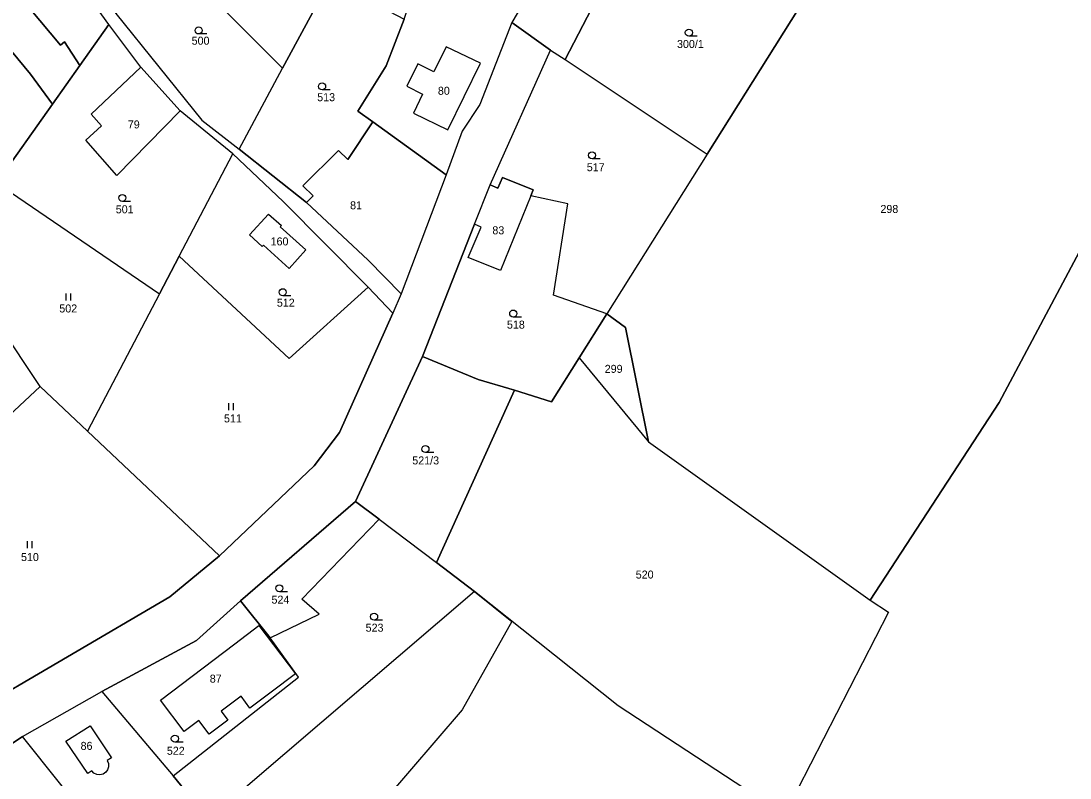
# Model space of a CAD drawing. Extents: x -590606 to -587796, y -1065936 to -1062515.
# Drawn here: x -589413.2 to -589190.3, y -1065080 to -1064919.2 of the extents above; entities that cross this region are included whole.
import ezdxf

# ---------------------------------------------------------------- set-up
doc = ezdxf.new("R2010")
doc.units = 0
for name, color, linetype in [('Parcela nároku', 7, 'Continuous'), ('Vnější obvod_ Studené', 7, 'Continuous'), ('Vrstva 30', 7, 'Continuous')]:
    doc.layers.add(name, color=color, linetype=linetype)

msp = doc.modelspace()

# ---------------------------------------------------------------- linework, layer by layer
at = {"layer": 'Parcela nároku'}
for points in [[(-589259.68, -1064827.84), (-589269.28, -1064848.75), (-589278.85, -1064866.5), (-589288.48, -1064884.36), (-589300.17, -1064904.53), (-589304.81, -1064912.46), (-589308.87, -1064919.53), (-589300.67, -1064925.35), (-589297.56, -1064927.36), (-589287.32, -1064907.52), (-589281.16, -1064895.58), (-589279.95, -1064893.24), (-589262.31, -1064858.44), (-589251.32, -1064830.96)], [(-589222.78, -1064876.19), (-589246.47, -1064914.08), (-589267.42, -1064947.46), (-589288.75, -1064981.4), (-589284.72, -1064984.27), (-589279.85, -1065008.58), (-589232.77, -1065042.25), (-589205.41, -1065000.22), (-589178.94, -1064950.61), (-589164.98, -1064928.86), (-589195.94, -1064838.44)], [(-589419.51, -1064880.71), (-589429.73, -1064863.35), (-589441.1, -1064876.11), (-589455.18, -1064891.01), (-589467.9, -1064901.87), (-589466.69, -1064904.1), (-589451.25, -1064936.39), (-589448.63, -1064940.01), (-589428.23, -1064968.24), (-589418.35, -1064953.57), (-589406.51, -1064936.87), (-589411.18, -1064930.48), (-589420.99, -1064918.63), (-589422.85, -1064920.26), (-589426.28, -1064916.08), (-589417.57, -1064908.93), (-589404.77, -1064924.29), (-589403.91, -1064923.64), (-589400.68, -1064928.65), (-589394.5, -1064919.94), (-589399.91, -1064912.39), (-589408.85, -1064896.13)], [(-589383.76, -1064903.01), (-589373.39, -1064885.02), (-589347.99, -1064911.38), (-589357.61, -1064929.21)], [(-589279.95, -1064893.24), (-589281.16, -1064895.58), (-589278.68, -1064897.05), (-589272.09, -1064900.96), (-589278.62, -1064912.48), (-589285.08, -1064908.8), (-589287.32, -1064907.52), (-589297.56, -1064927.36), (-589267.42, -1064947.46), (-589246.47, -1064914.08)], [(-589357.61, -1064929.21), (-589383.76, -1064903.01), (-589393.02, -1064917.62), (-589374.79, -1064940.23), (-589366.84, -1064946.39)], [(-589335.57, -1064928.69), (-589331.74, -1064918.83), (-589330.41, -1064914.67), (-589321.7, -1064902.7), (-589304.81, -1064912.46), (-589308.87, -1064919.53), (-589315.72, -1064936.94), (-589319.44, -1064942.57), (-589322.86, -1064951.87), (-589338.42, -1064940.59), (-589341.61, -1064938.33)], [(-589403.91, -1064923.64), (-589404.77, -1064924.29), (-589417.57, -1064908.93), (-589426.28, -1064916.08), (-589422.85, -1064920.26), (-589420.99, -1064918.63), (-589411.18, -1064930.48), (-589406.51, -1064936.87), (-589400.68, -1064928.65)], [(-589366.84, -1064946.39), (-589357.61, -1064929.21), (-589347.99, -1064911.38), (-589347.53, -1064910.53), (-589331.74, -1064918.83), (-589335.57, -1064928.69), (-589341.61, -1064938.33), (-589338.42, -1064940.59), (-589343.75, -1064948.59), (-589345.73, -1064946.7), (-589353.29, -1064954.21), (-589351.12, -1064956.35), (-589352.52, -1064957.78)], [(-589396.04, -1064941.45), (-589398.25, -1064938.99), (-589387.73, -1064929), (-589394.5, -1064919.94), (-589400.68, -1064928.65), (-589406.51, -1064936.87), (-589418.35, -1064953.57), (-589383.75, -1064977.12), (-589379.59, -1064969.17), (-589368.16, -1064947.4), (-589379.39, -1064938.24), (-589392.85, -1064951.99), (-589399.41, -1064944.5)], [(-589315.54, -1064928.15), (-589322.84, -1064924.67), (-589325.45, -1064930.01), (-589328.89, -1064928.32), (-589331.22, -1064933.05), (-589327.85, -1064934.75), (-589329.8, -1064938.77), (-589322.52, -1064942.32)], [(-589329.8, -1064938.77), (-589322.52, -1064942.32), (-589315.54, -1064928.15), (-589322.84, -1064924.67), (-589325.45, -1064930.01), (-589328.89, -1064928.32), (-589331.22, -1064933.05), (-589327.85, -1064934.75)], [(-589313.53, -1064953.98), (-589300.67, -1064925.35), (-589297.56, -1064927.36), (-589267.42, -1064947.46), (-589288.75, -1064981.4), (-589300.06, -1064977.43), (-589297.02, -1064958), (-589304.88, -1064956.35), (-589304.36, -1064955.07), (-589310.89, -1064952.43), (-589311.87, -1064954.72)], [(-589398.25, -1064938.99), (-589387.73, -1064929), (-589379.39, -1064938.24), (-589392.85, -1064951.99), (-589399.41, -1064944.5), (-589396.04, -1064941.45)], [(-589164.98, -1064928.86), (-589178.94, -1064950.61), (-589205.41, -1065000.22), (-589232.77, -1065042.25), (-589228.87, -1065044.77), (-589250.95, -1065087.85), (-589277.85, -1065125.06), (-589252.37, -1065158.64), (-589245.33, -1065170.48), (-589231.95, -1065203.34), (-589224.84, -1065238.37), (-589201.19, -1065210.22), (-589196.32, -1065193.25), (-589184.2, -1065137.36), (-589161.34, -1065072.9), (-589151.23, -1065033.97), (-589150.92, -1065007.3), (-589154.33, -1064973.17)], [(-589345.73, -1064946.7), (-589343.75, -1064948.59), (-589338.42, -1064940.59), (-589322.86, -1064951.87), (-589332.39, -1064977.16), (-589339.41, -1064969.99), (-589352.52, -1064957.78), (-589351.12, -1064956.35), (-589353.29, -1064954.21)], [(-589379.59, -1064969.17), (-589368.16, -1064947.4), (-589357.48, -1064957.56), (-589339.45, -1064975.71), (-589356.17, -1064990.92)], [(-589318.17, -1064969.4), (-589315.41, -1064962.97), (-589316.85, -1064962.35), (-589313.53, -1064953.98), (-589311.87, -1064954.72), (-589310.89, -1064952.43), (-589304.36, -1064955.07), (-589304.88, -1064956.35), (-589311.29, -1064972.21)], [(-589418.35, -1064953.57), (-589383.75, -1064977.12), (-589399.02, -1065006.32), (-589409.1, -1064996.85), (-589426.46, -1064970.88), (-589428.23, -1064968.24)], [(-589311.29, -1064972.21), (-589318.17, -1064969.4), (-589315.41, -1064962.97), (-589316.85, -1064962.35), (-589327.88, -1064990.45), (-589316.08, -1064995.33), (-589308.34, -1064997.6), (-589300.48, -1065000.08), (-589294.61, -1064990.73), (-589288.75, -1064981.4), (-589300.06, -1064977.43), (-589297.02, -1064958), (-589304.88, -1064956.35)], [(-589356.21, -1064971.76), (-589361.69, -1064966.82), (-589361.91, -1064967.07), (-589364.6, -1064964.65), (-589360.57, -1064960.19), (-589357.86, -1064962.64), (-589358.09, -1064962.9), (-589352.64, -1064967.82)], [(-589358.09, -1064962.9), (-589352.64, -1064967.82), (-589356.21, -1064971.76), (-589361.69, -1064966.82), (-589361.91, -1064967.07), (-589364.6, -1064964.65), (-589360.57, -1064960.19), (-589357.86, -1064962.64)], [(-589339.45, -1064975.71), (-589356.17, -1064990.92), (-589379.59, -1064969.17), (-589383.75, -1064977.12), (-589399.02, -1065006.32), (-589371.02, -1065032.81), (-589350.89, -1065013.72), (-589345.5, -1065006.58), (-589334.15, -1064981.25)], [(-589409.1, -1064996.85), (-589426.46, -1064970.88), (-589431.86, -1064975.44), (-589474.4, -1065009.98), (-589466.26, -1065019.11), (-589460.55, -1065012.72), (-589456.29, -1065016.72), (-589453.72, -1065013.94), (-589446.47, -1065020.23), (-589449.1, -1065023.14), (-589443.26, -1065028.68)], [(-589288.75, -1064981.4), (-589294.61, -1064990.73), (-589279.85, -1065008.58), (-589284.72, -1064984.27)], [(-589316.08, -1064995.33), (-589327.88, -1064990.45), (-589342.09, -1065021.3), (-589337.1, -1065025.05), (-589324.9, -1065034.23), (-589308.34, -1064997.6)], [(-589232.77, -1065042.25), (-589228.87, -1065044.77), (-589250.95, -1065087.85), (-589286.33, -1065064.68), (-589316.82, -1065040.39), (-589324.9, -1065034.23), (-589308.34, -1064997.6), (-589300.48, -1065000.08), (-589294.61, -1064990.73), (-589279.85, -1065008.58)], [(-589399.02, -1065006.32), (-589409.1, -1064996.85), (-589443.26, -1065028.68), (-589451.81, -1065036.64), (-589425.07, -1065067.02), (-589381.58, -1065041.51), (-589371.02, -1065032.81)], [(-589342.09, -1065021.3), (-589366.54, -1065042.39), (-589360.23, -1065050.24), (-589349.8, -1065045.2), (-589353.53, -1065041.99), (-589337.1, -1065025.05)], [(-589360.23, -1065050.24), (-589349.8, -1065045.2), (-589353.53, -1065041.99), (-589337.1, -1065025.05), (-589324.9, -1065034.23), (-589316.82, -1065040.39), (-589373.33, -1065088.79), (-589380.88, -1065079.54), (-589354.19, -1065058.62)], [(-589286.33, -1065064.68), (-589316.82, -1065040.39), (-589373.33, -1065088.79), (-589324.71, -1065146.34), (-589291.24, -1065107.19), (-589277.85, -1065125.06), (-589250.95, -1065087.85)], [(-589354.19, -1065058.62), (-589360.23, -1065050.24), (-589366.54, -1065042.39), (-589375.89, -1065050.78), (-589396, -1065061.67), (-589380.88, -1065079.54)], [(-589383.53, -1065063.51), (-589367.72, -1065051.52), (-589362.62, -1065047.65), (-589354.84, -1065057.9), (-589360.05, -1065061.81), (-589364.53, -1065065.17), (-589366.43, -1065062.63), (-589370.68, -1065065.82), (-589369.24, -1065067.74), (-589373.2, -1065070.71), (-589375.38, -1065067.8), (-589378.53, -1065070.17)], [(-589364.53, -1065065.17), (-589366.43, -1065062.63), (-589370.68, -1065065.82), (-589369.24, -1065067.74), (-589373.2, -1065070.71), (-589375.38, -1065067.8), (-589378.53, -1065070.17), (-589383.53, -1065063.51), (-589367.72, -1065051.52), (-589362.62, -1065047.65), (-589354.84, -1065057.9), (-589360.05, -1065061.81)], [(-589380.88, -1065079.54), (-589373.33, -1065088.79), (-589389.87, -1065100.03), (-589412.82, -1065071.17), (-589396, -1065061.67)], [(-589403.68, -1065072.19), (-589398.49, -1065068.9), (-589393.95, -1065075.73), (-589394.84, -1065076.32), (-589394.59, -1065076.95), (-589394.57, -1065077.62), (-589394.78, -1065078.26), (-589395.18, -1065078.8), (-589395.74, -1065079.17), (-589396.4, -1065079.33), (-589397.07, -1065079.27), (-589397.68, -1065078.98), (-589398.16, -1065078.51), (-589398.97, -1065079.04)], [(-589398.16, -1065078.51), (-589398.97, -1065079.04), (-589403.68, -1065072.19), (-589398.49, -1065068.9), (-589393.95, -1065075.73), (-589394.84, -1065076.32), (-589394.59, -1065076.95), (-589394.57, -1065077.62), (-589394.78, -1065078.26), (-589395.18, -1065078.8), (-589395.74, -1065079.17), (-589396.4, -1065079.33), (-589397.07, -1065079.27), (-589397.68, -1065078.98)], [(-589389.87, -1065100.03), (-589412.82, -1065071.17), (-589432.22, -1065084.17), (-589431.18, -1065086.73), (-589428.43, -1065092.41), (-589422.14, -1065099.19), (-589378.86, -1065152.89), (-589352.63, -1065182.93), (-589324.71, -1065146.34), (-589373.33, -1065088.79)]]:
    msp.add_lwpolyline(points, close=True, dxfattribs=at)
for points in [[(-589416.34, -1064879.6), (-589405.49, -1064893.12), (-589402.24, -1064899.51), (-589395.57, -1064913.49), (-589393.02, -1064917.62), (-589374.79, -1064940.23), (-589366.84, -1064946.39), (-589352.52, -1064957.78), (-589339.41, -1064969.99), (-589332.39, -1064977.16), (-589334.15, -1064981.25), (-589339.45, -1064975.71), (-589357.48, -1064957.56), (-589368.16, -1064947.4), (-589379.39, -1064938.24), (-589387.73, -1064929), (-589394.5, -1064919.94), (-589399.91, -1064912.39), (-589408.85, -1064896.13), (-589419.51, -1064880.71)], [(-589432.22, -1065084.17), (-589412.82, -1065071.17), (-589396, -1065061.67), (-589375.89, -1065050.78), (-589366.54, -1065042.39), (-589342.09, -1065021.3), (-589327.88, -1064990.45), (-589316.85, -1064962.35), (-589313.53, -1064953.98), (-589300.67, -1064925.35), (-589308.87, -1064919.53), (-589315.72, -1064936.94), (-589319.44, -1064942.57), (-589322.86, -1064951.87), (-589332.39, -1064977.16), (-589334.15, -1064981.25), (-589345.5, -1065006.58), (-589350.89, -1065013.72), (-589371.02, -1065032.81), (-589381.58, -1065041.51), (-589425.07, -1065067.02), (-589428.09, -1065070.14), (-589445.82, -1065082.83)]]:
    msp.add_lwpolyline(points, dxfattribs=at)
at = {"layer": 'Vnější obvod_ Studené'}
for p, q in [((-589246.47, -1064914.08), (-589267.42, -1064947.46)), ((-589267.42, -1064947.46), (-589288.75, -1064981.4)), ((-589288.75, -1064981.4), (-589294.61, -1064990.73)), ((-589294.61, -1064990.73), (-589300.48, -1065000.08)), ((-589308.34, -1064997.6), (-589324.9, -1065034.23)), ((-589300.48, -1065000.08), (-589308.34, -1064997.6)), ((-589324.9, -1065034.23), (-589316.82, -1065040.39)), ((-589316.82, -1065040.39), (-589308.87, -1065046.73)), ((-589308.87, -1065046.73), (-589319.48, -1065065.54)), ((-589319.48, -1065065.54), (-589337.78, -1065086.88))]:
    msp.add_line(p, q, dxfattribs=at)
at = {"layer": 'Vrstva 30'}
for p, q in [((-589373.69, -1064921.94), (-589375.44, -1064921.94)), ((-589269.55, -1064922.41), (-589271.3, -1064922.41)), ((-589347.46, -1064933.83), (-589349.21, -1064933.83)), ((-589290.12, -1064948.47), (-589291.87, -1064948.47)), ((-589389.89, -1064957.53), (-589391.64, -1064957.53)), ((-589403.64, -1064977.1), (-589403.64, -1064978.6)), ((-589402.61, -1064978.6), (-589402.61, -1064977.1)), ((-589355.82, -1064977.56), (-589357.57, -1064977.56)), ((-589306.86, -1064982.09), (-589308.61, -1064982.09)), ((-589369.08, -1065000.39), (-589369.08, -1065001.89)), ((-589368.06, -1065001.89), (-589368.06, -1065000.39)), ((-589325.5, -1065010.88), (-589327.25, -1065010.88)), ((-589411.83, -1065029.72), (-589411.83, -1065031.22)), ((-589410.81, -1065031.22), (-589410.81, -1065029.72)), ((-589356.54, -1065040.46), (-589358.29, -1065040.46)), ((-589336.41, -1065046.48), (-589338.16, -1065046.48)), ((-589378.74, -1065072.4), (-589380.49, -1065072.4))]:
    msp.add_line(p, q, dxfattribs=at)
for centre in [(-589375.44, -1064921.19), (-589271.3, -1064921.66), (-589349.21, -1064933.08), (-589291.87, -1064947.72), (-589391.64, -1064956.78), (-589357.57, -1064976.81), (-589308.61, -1064981.34), (-589327.25, -1065010.13), (-589358.29, -1065039.71), (-589338.16, -1065045.73), (-589380.49, -1065071.65)]:
    msp.add_circle(centre, 0.75, dxfattribs=at)

# ---------------------------------------------------------------- texts
at = {"layer": 'Parcela nároku'}
for s, p in [('500', (-589376.92, -1064924.22)), ('300/1', (-589273.81, -1064924.92)), ('513', (-589350.25, -1064936.22)), ('80', (-589324.61, -1064934.86)), ('79', (-589390.48, -1064942.01)), ('517', (-589292.98, -1064951.09)), ('501', (-589393.04, -1064960.04)), ('81', (-589343.26, -1064959.19)), ('298', (-589230.6, -1064959.97)), ('83', (-589313.04, -1064964.5)), ('160', (-589360.15, -1064966.86)), ('502', (-589405.03, -1064981.11)), ('512', (-589358.82, -1064979.88)), ('518', (-589309.94, -1064984.54)), ('299', (-589289.17, -1064993.94)), ('511', (-589370.05, -1065004.47)), ('521/3', (-589330.05, -1065013.39)), ('510', (-589413.17, -1065033.92)), ('520', (-589282.58, -1065037.64)), ('524', (-589359.96, -1065042.97)), ('523', (-589339.96, -1065048.93)), ('87', (-589373.07, -1065059.75)), ('86', (-589400.51, -1065074.04)), ('522', (-589382.19, -1065075.08))]:
    msp.add_text(s, height=1.7, dxfattribs=at).set_placement(p)

doc.saveas('drawing.dxf')
